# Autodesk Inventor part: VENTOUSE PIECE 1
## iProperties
Created: 2004-11
Part Number: VENTOUSE PIECE 1
Document SubType Name: Modeling
Designer: Bruno
Manufacturer: Standard
Standards Organization: Custom
Author: Bruno
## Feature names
1. Base1
